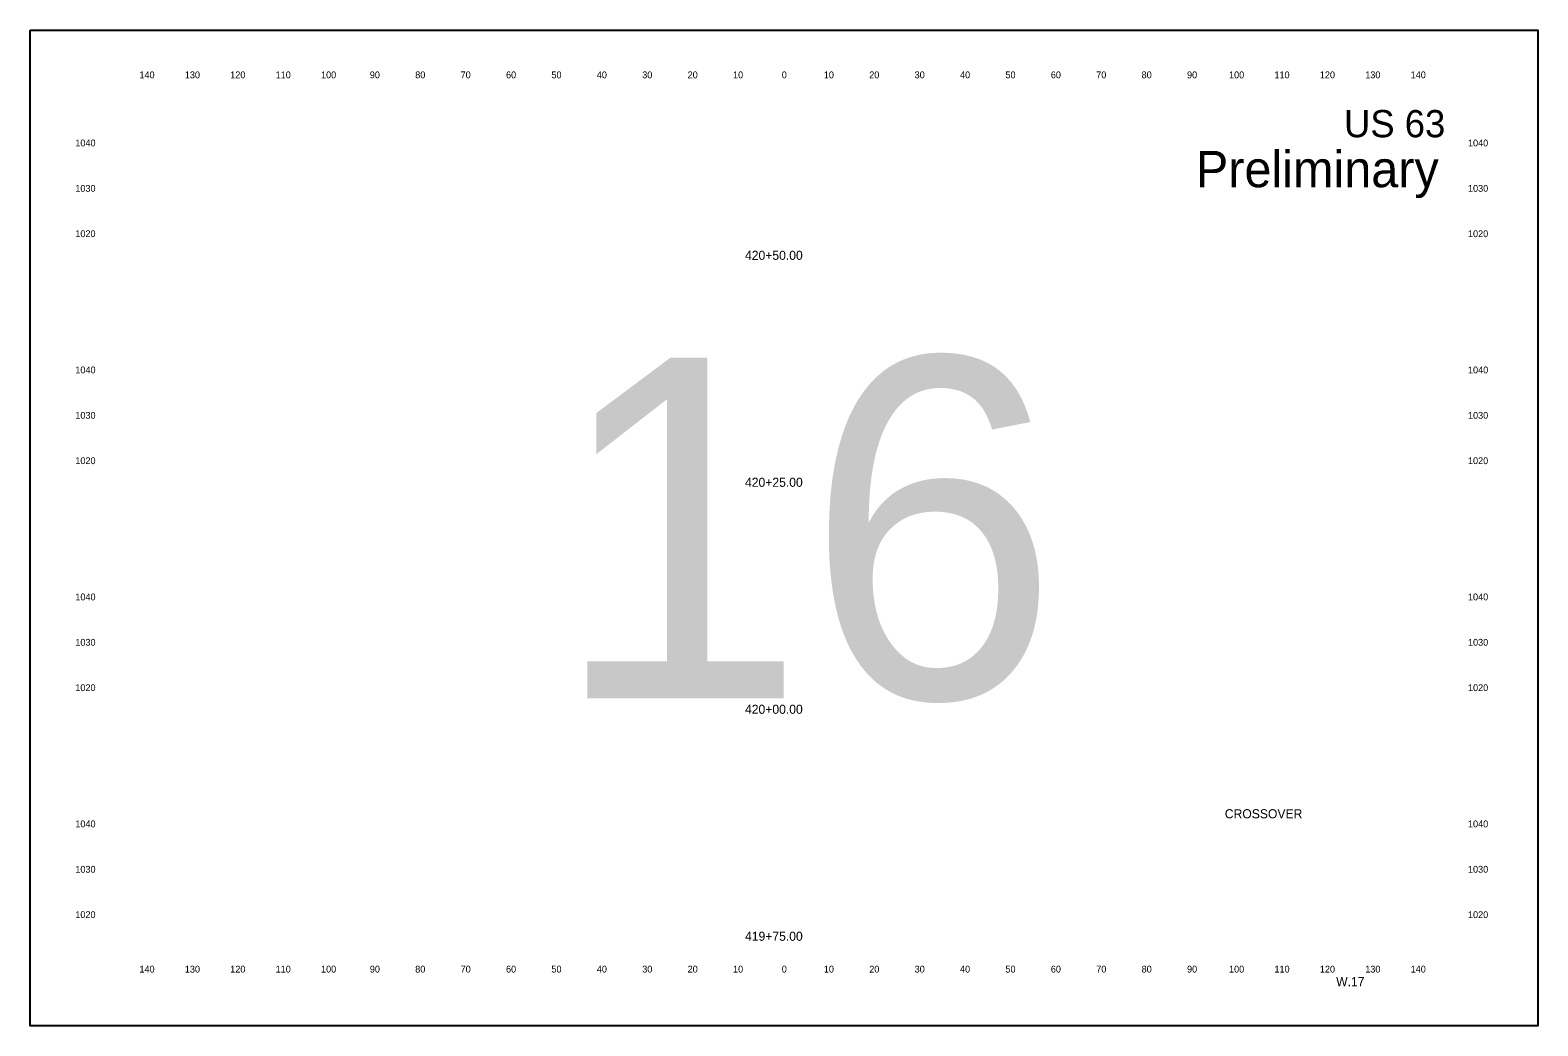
# Model space of a CAD drawing. Extents: x 10123 to 17295, y 9730 to 10181.
# Drawn here: x 15523.2 to 15855.3, y 9730.3 to 9949.6 of the extents above; entities that cross this region are included whole.
import ezdxf

# ---------------------------------------------------------------- set-up
doc = ezdxf.new("R2010")
doc.units = 0
for name, color, linetype in [('dsnTextCpn', 7, 'Continuous'), ('dsnTextCpnTitleSheetLocDesc', 7, 'Continuous'), ('dsnTextCpnTitleSheetPIN', 7, 'Continuous'), ('dsnTextCpnTitleSheetWorkType', 7, 'Continuous')]:
    doc.layers.add(name, color=color, linetype=linetype)

msp = doc.modelspace()

# ---------------------------------------------------------------- linework, layer by layer
at = {"layer": 'dsnTextCpnTitleSheetWorkType'}
msp.add_lwpolyline([(15523.21, 9949.6), (15855.29, 9949.6), (15855.29, 9730.26), (15523.21, 9730.26)], close=True, dxfattribs=at)

# ---------------------------------------------------------------- texts
at = {"layer": 'dsnTextCpn'}
for s, height, p in [('140', 1.5, (15547.27, 9939)), ('130', 1.5, (15557.27, 9939)), ('120', 1.5, (15567.27, 9939)), ('110', 1.5, (15577.27, 9939)), ('100', 1.5, (15587.27, 9939)), ('90', 1.5, (15598.02, 9939)), ('80', 1.5, (15608.02, 9939)), ('70', 1.5, (15618.02, 9939)), ('60', 1.5, (15628.02, 9939)), ('50', 1.5, (15638.02, 9939)), ('40', 1.5, (15648.02, 9939)), ('30', 1.5, (15658.02, 9939)), ('20', 1.5, (15668.02, 9939)), ('10', 1.5, (15678.02, 9939)), ('0', 1.5, (15688.76, 9939)), ('0', 1.5, (15688.76, 9939)), ('10', 1.5, (15698.02, 9939)), ('20', 1.5, (15708.02, 9939)), ('30', 1.5, (15718.02, 9939)), ('40', 1.5, (15728.02, 9939)), ('50', 1.5, (15738.02, 9939)), ('60', 1.5, (15748.02, 9939)), ('70', 1.5, (15758.02, 9939)), ('80', 1.5, (15768.02, 9939)), ('90', 1.5, (15778.02, 9939)), ('100', 1.5, (15787.27, 9939)), ('110', 1.5, (15797.27, 9939)), ('120', 1.5, (15807.27, 9939)), ('130', 1.5, (15817.27, 9939)), ('140', 1.5, (15827.27, 9939)), ('US 63', 6, (15812.6, 9926)), ('1040', 1.5, (15533.15, 9924)), ('1040', 1.5, (15839.9, 9924)), ('1030', 1.5, (15533.15, 9914)), ('1030', 1.5, (15839.9, 9914)), ('1020', 1.5, (15533.15, 9904)), ('1020', 1.5, (15839.9, 9904)), ('420+50.00', 2, (15680.66, 9899)), ('1040', 1.5, (15533.15, 9874)), ('1040', 1.5, (15839.9, 9874)), ('1030', 1.5, (15533.15, 9864)), ('1030', 1.5, (15839.9, 9864)), ('1020', 1.5, (15533.15, 9854)), ('1020', 1.5, (15839.9, 9854)), ('420+25.00', 2, (15680.66, 9849)), ('1040', 1.5, (15533.15, 9824)), ('1040', 1.5, (15839.9, 9824)), ('1030', 1.5, (15533.15, 9814)), ('1030', 1.5, (15839.9, 9814)), ('1020', 1.5, (15533.15, 9804)), ('1020', 1.5, (15839.9, 9804)), ('420+00.00', 2, (15680.66, 9799)), ('CROSSOVER', 2, (15786.34, 9775.98)), ('1040', 1.5, (15533.15, 9774)), ('1040', 1.5, (15839.9, 9774)), ('1030', 1.5, (15533.15, 9764)), ('1030', 1.5, (15839.9, 9764)), ('1020', 1.5, (15533.15, 9754)), ('1020', 1.5, (15839.9, 9754)), ('419+75.00', 2, (15680.66, 9749)), ('140', 1.5, (15547.27, 9742)), ('130', 1.5, (15557.27, 9742)), ('120', 1.5, (15567.27, 9742)), ('110', 1.5, (15577.27, 9742)), ('100', 1.5, (15587.27, 9742)), ('90', 1.5, (15598.02, 9742)), ('80', 1.5, (15608.02, 9742)), ('70', 1.5, (15618.02, 9742)), ('60', 1.5, (15628.02, 9742)), ('50', 1.5, (15638.02, 9742)), ('40', 1.5, (15648.02, 9742)), ('30', 1.5, (15658.02, 9742)), ('20', 1.5, (15668.02, 9742)), ('10', 1.5, (15678.02, 9742)), ('0', 1.5, (15688.76, 9742)), ('0', 1.5, (15688.76, 9742)), ('10', 1.5, (15698.02, 9742)), ('20', 1.5, (15708.02, 9742)), ('30', 1.5, (15718.02, 9742)), ('40', 1.5, (15728.02, 9742)), ('50', 1.5, (15738.02, 9742)), ('60', 1.5, (15748.02, 9742)), ('70', 1.5, (15758.02, 9742)), ('80', 1.5, (15768.02, 9742)), ('90', 1.5, (15778.02, 9742)), ('100', 1.5, (15787.27, 9742)), ('110', 1.5, (15797.27, 9742)), ('120', 1.5, (15807.27, 9742)), ('130', 1.5, (15817.27, 9742)), ('140', 1.5, (15827.27, 9742))]:
    msp.add_text(s, height=height, dxfattribs=at).set_placement(p)
at = {"layer": 'dsnTextCpnTitleSheetLocDesc'}
msp.add_text('Preliminary', height=8, dxfattribs=at).set_placement((15779.97, 9915))
at = {"layer": 'dsnTextCpnTitleSheetPIN'}
msp.add_text('W.17', height=2, dxfattribs=at).set_placement((15810.87, 9739))
at = {"layer": 'dsnTextCpnTitleSheetWorkType'}
msp.add_text('16', height=75, dxfattribs=at).set_placement((15638.26, 9802.43))

doc.saveas('drawing.dxf')
